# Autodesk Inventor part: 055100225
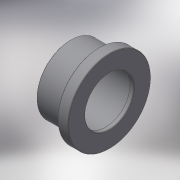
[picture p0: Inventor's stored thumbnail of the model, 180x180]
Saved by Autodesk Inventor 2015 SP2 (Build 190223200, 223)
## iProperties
Created: 2017-10
Part Number: 055100225
Material: Generic
Description: PLASSON FLANGE FLAT AD.-CEM 225
Document SubType Name: Modeling
Designer: KIM
Mass: 1343.9 g
Surface Area: 2365.31 cm^2
Volume: 1343.9 cm^3
Density: 1 g/cm^3
Appearance: Default
Author: KIM
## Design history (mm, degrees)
derived "055100.ipt"
feature "Solid1::055100.ipt"
tag "TaggingFeature1"
body "Solid1"
other parameters: "d0" = 126, "d1" = 249, "d2" = 225, "d3" = 202.5, "d4" = 18, "d5" = 119, "d6" = 272, "d8" = 2.25, "d_" = 225, "E_" = 249, "E_1" = 272, "l_" = 119, "B_" = 18, "H_" = 126
